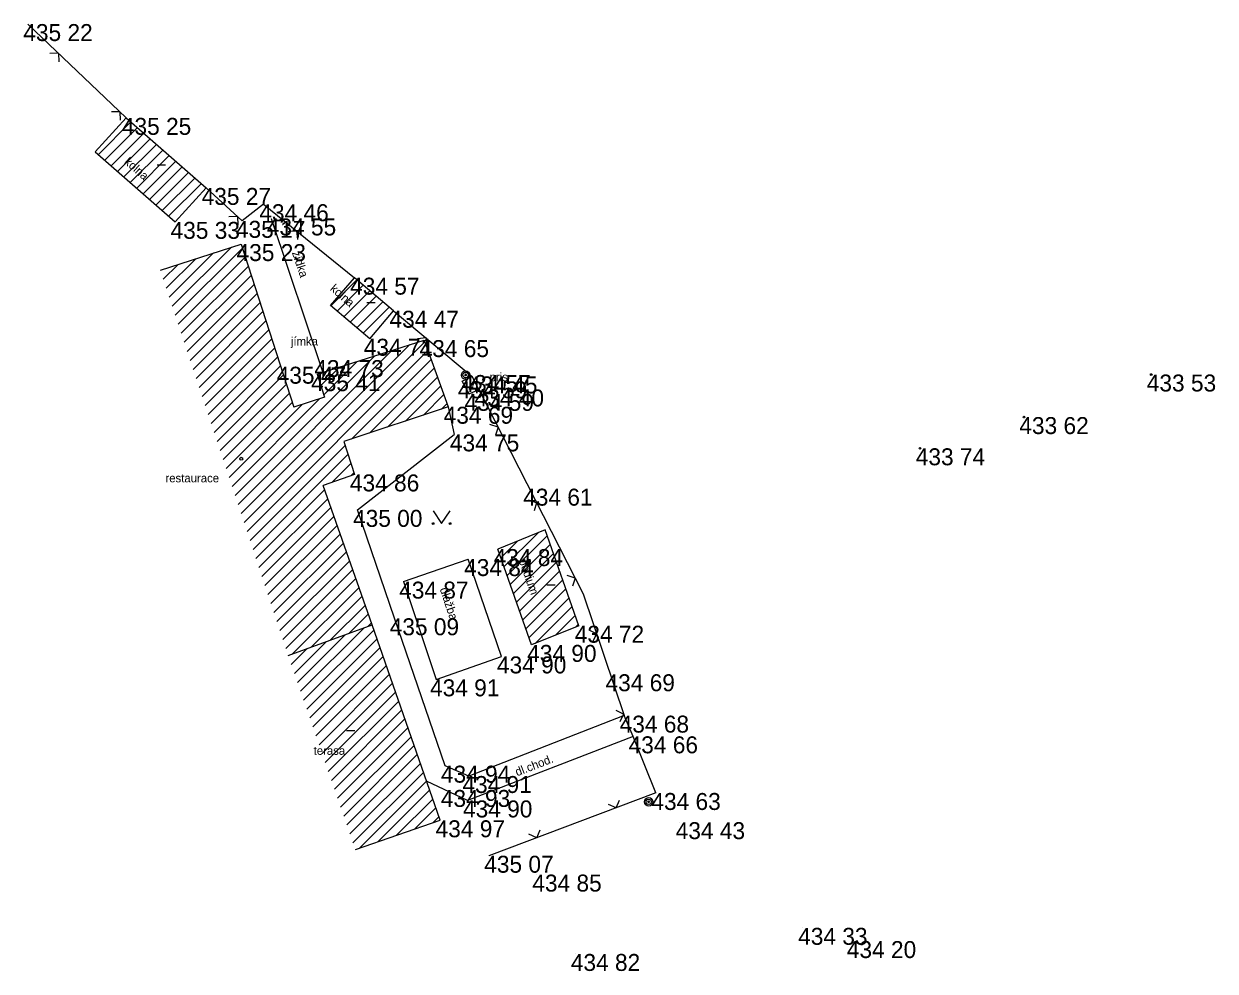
# Model space of a CAD drawing. Extents: x -554123 to -553118, y -1076825 to -1073672.
# Drawn here: x -554023.6 to -553953.4, y -1074082.7 to -1074026.9 of the extents above; entities that cross this region are included whole.
import ezdxf

# ---------------------------------------------------------------- set-up
doc = ezdxf.new("R2010")
doc.units = 0
for name, color, linetype in [('1', 7, 'Continuous'), ('12', 7, 'Continuous'), ('14', 7, 'Continuous'), ('17', 7, 'Continuous'), ('18', 7, 'Continuous'), ('20', 7, 'Continuous'), ('32', 7, 'Continuous'), ('45', 7, 'Continuous'), ('47', 7, 'Continuous'), ('52', 7, 'Continuous'), ('6', 7, 'Continuous')]:
    doc.layers.add(name, color=color, linetype=linetype)

# ---------------------------------------------------------------- blocks, each defined once
blk = doc.blocks.new('POINT_DISPLAY')
blk.add_line((0, 0), (0, 0))
blk = doc.blocks.new('T')
at = {"layer": '6'}
blk.add_circle((0, 0), 0.05, dxfattribs=at)
blk = doc.blocks.new('SLB')
at = {"layer": '20'}
for radius in [0.25, 0.158, 0.05]:
    blk.add_circle((0, 0), radius, dxfattribs=at)
blk = doc.blocks.new('BN')
at = {"layer": '47'}
blk.add_line((-0.25, 0), (0.25, 0), dxfattribs=at)
blk = doc.blocks.new('BZ')
at = {"layer": '47'}
blk.add_circle((0, 0), 0.0875, dxfattribs=at)
blk = doc.blocks.new('PARK')
at = {"layer": '45'}
for p, q in [((-0.5, 0.75), (0, 0)), ((0, 0), (0.5, 0.75))]:
    blk.add_line(p, q, dxfattribs=at)
for centre in [(-0.5, 0), (0.5, 0)]:
    blk.add_circle(centre, 0.05, dxfattribs=at)

msp = doc.modelspace()

# ---------------------------------------------------------------- linework, layer by layer
at = {"layer": '12'}
for p, q in [((-554023.41, -1074026.87), (-554017.6, -1074032.4)), ((-554021.599, -1074028.594), (-554022.1, -1074028.606)), ((-554021.599, -1074028.594), (-554021.587, -1074029.094)), ((-554017.977, -1074032.041), (-554018.478, -1074032.053)), ((-554017.977, -1074032.041), (-554017.965, -1074032.541)), ((-554012.9, -1074036.53), (-554010.77, -1074038.47)), ((-554009.51, -1074037.49), (-554010.77, -1074038.47)), ((-554009.51, -1074037.49), (-554004.16, -1074041.82)), ((-554011.052, -1074038.213), (-554011.552, -1074038.237)), ((-554011.052, -1074038.213), (-554011.028, -1074038.713)), ((-554007.567, -1074039.063), (-554008.065, -1074039.115)), ((-554007.567, -1074039.063), (-554007.514, -1074039.561)), ((-554001.85, -1074043.77), (-553997.22, -1074047.64)), ((-553999.932, -1074045.373), (-554000.43, -1074045.418)), ((-553999.932, -1074045.373), (-553999.887, -1074045.872)), ((-553996.83, -1074048.41), (-553990.676, -1074060.449)), ((-553995.692, -1074050.636), (-553996.168, -1074050.482)), ((-553995.692, -1074050.636), (-553995.846, -1074051.112)), ((-553993.416, -1074055.088), (-553993.893, -1074054.934)), ((-553993.416, -1074055.088), (-553993.57, -1074055.564)), ((-553991.141, -1074059.54), (-553991.617, -1074059.386)), ((-553991.141, -1074059.54), (-553991.295, -1074060.016)), ((-553990.676, -1074060.449), (-553988.26, -1074067.64)), ((-553989.88, -1074062.819), (-553990.328, -1074062.596)), ((-553989.88, -1074062.819), (-553990.103, -1074063.267)), ((-553988.287, -1074067.558), (-553988.736, -1074067.336)), ((-553988.287, -1074067.558), (-553988.51, -1074068.007)), ((-553987.72, -1074068.86), (-553988.26, -1074067.64)), ((-553986.39, -1074072.2), (-553987.72, -1074068.86)), ((-553986.39, -1074072.2), (-553996.24, -1074075.9)), ((-553988.73, -1074073.079), (-553989.186, -1074072.872)), ((-553988.73, -1074073.079), (-553988.523, -1074072.623)), ((-553993.411, -1074074.837), (-553993.204, -1074074.381)), ((-553993.411, -1074074.837), (-553993.867, -1074074.63))]:
    msp.add_line(p, q, dxfattribs=at)
at = {"layer": '14'}
for p, q in [((-554017.6, -1074032.4), (-554019.43, -1074034.4)), ((-554017.6, -1074032.4), (-554012.9, -1074036.53)), ((-554019.43, -1074034.4), (-554014.73, -1074038.53)), ((-554012.9, -1074036.53), (-554014.73, -1074038.53)), ((-554015.595, -1074041.385), (-554010.84, -1074039.84)), ((-554010.84, -1074039.84), (-554007.718, -1074049.447)), ((-554005.56, -1074043.47), (-554004.16, -1074041.82)), ((-554001.85, -1074043.77), (-554004.16, -1074041.82)), ((-554003.25, -1074045.42), (-554005.56, -1074043.47)), ((-554003.25, -1074045.42), (-554001.85, -1074043.77)), ((-554006.35, -1074047.51), (-554000.05, -1074045.5)), ((-554000.05, -1074045.5), (-553998.62, -1074049.43)), ((-554006.35, -1074047.51), (-554005.911, -1074048.86)), ((-554005.911, -1074048.86), (-554007.718, -1074049.447)), ((-553998.62, -1074049.43), (-554004.777, -1074051.485)), ((-554004.777, -1074051.485), (-554004.16, -1074053.42)), ((-554004.16, -1074053.42), (-554006.006, -1074054.074)), ((-554003.1, -1074062.28), (-554006.006, -1074054.074)), ((-553992.92, -1074056.69), (-553995.71, -1074057.82)), ((-553990.92, -1074062.34), (-553992.92, -1074056.69)), ((-553993.71, -1074063.47), (-553995.71, -1074057.82)), ((-554008.057, -1074064.101), (-554003.1, -1074062.28)), ((-553999.11, -1074073.81), (-554003.1, -1074062.28)), ((-553990.92, -1074062.34), (-553993.71, -1074063.47)), ((-554004.1, -1074075.537), (-553999.11, -1074073.81))]:
    msp.add_line(p, q, dxfattribs=at)
at = {"layer": '17'}
for p, q in [((-553998.62, -1074049.43), (-553998.28, -1074051.06)), ((-554003.97, -1074055.51), (-553998.28, -1074051.06)), ((-554001.8, -1074061.9), (-554003.97, -1074055.51)), ((-554001.27, -1074059.74), (-553997.45, -1074058.41)), ((-553995.49, -1074064.15), (-553997.45, -1074058.41)), ((-554001.27, -1074059.74), (-553999.33, -1074065.5)), ((-553998.81, -1074070.59), (-554001.8, -1074061.9)), ((-553999.33, -1074065.5), (-553995.49, -1074064.15)), ((-553988.26, -1074067.64), (-553997.42, -1074071.2)), ((-553987.72, -1074068.86), (-553997.49, -1074072.64)), ((-553997.42, -1074071.2), (-553998.81, -1074070.59)), ((-553997.49, -1074072.64), (-553999.911, -1074071.494))]:
    msp.add_line(p, q, dxfattribs=at)
at = {"layer": '18'}
for p, q in [((-554009.07, -1074038.33), (-554006.026, -1074047.407)), ((-553997.8, -1074047.93), (-553997.22, -1074047.64)), ((-553996.83, -1074048.41), (-553997.22, -1074047.64)), ((-553997.4, -1074048.67), (-553997.8, -1074047.93)), ((-553997.4, -1074048.67), (-553996.83, -1074048.41))]:
    msp.add_line(p, q, dxfattribs=at)
at = {"layer": '32'}
for p, q in [((-554019.247, -1074034.561), (-554017.326, -1074032.641)), ((-554018.87, -1074034.892), (-554016.95, -1074032.971)), ((-554018.494, -1074035.223), (-554016.573, -1074033.302)), ((-554018.117, -1074035.553), (-554016.197, -1074033.633)), ((-554017.741, -1074035.884), (-554015.821, -1074033.964)), ((-554017.365, -1074036.215), (-554015.444, -1074034.294)), ((-554016.988, -1074036.546), (-554015.068, -1074034.625)), ((-554016.612, -1074036.876), (-554014.691, -1074034.956)), ((-554016.236, -1074037.207), (-554014.315, -1074035.287)), ((-554015.859, -1074037.538), (-554013.939, -1074035.617)), ((-554015.483, -1074037.869), (-554013.562, -1074035.948)), ((-554015.106, -1074038.199), (-554013.186, -1074036.279)), ((-554014.89, -1074043.509), (-554011.405, -1074040.024)), ((-554014.714, -1074044.04), (-554010.76, -1074040.086)), ((-554015.243, -1074042.447), (-554013.5, -1074040.704)), ((-554015.066, -1074042.978), (-554012.453, -1074040.364)), ((-554014.538, -1074044.571), (-554010.587, -1074040.619)), ((-554015.419, -1074041.916), (-554014.548, -1074041.045)), ((-554014.362, -1074045.101), (-554010.413, -1074041.153)), ((-554014.186, -1074045.632), (-554010.24, -1074041.687)), ((-554014.009, -1074046.163), (-554010.066, -1074042.22)), ((-554005.551, -1074043.478), (-554004.015, -1074041.942)), ((-554005.167, -1074043.802), (-554003.632, -1074042.266)), ((-554013.833, -1074046.694), (-554009.893, -1074042.754)), ((-554004.784, -1074044.125), (-554003.248, -1074042.59)), ((-554004.4, -1074044.449), (-554002.865, -1074042.913)), ((-554013.657, -1074047.225), (-554009.72, -1074043.288)), ((-554004.017, -1074044.773), (-554002.481, -1074043.237)), ((-554003.633, -1074045.096), (-554002.098, -1074043.561)), ((-554013.481, -1074047.756), (-554009.546, -1074043.821)), ((-554013.305, -1074048.287), (-554009.373, -1074044.355)), ((-554013.128, -1074048.818), (-554009.199, -1074044.889)), ((-554012.952, -1074049.349), (-554009.026, -1074045.422)), ((-554010.838, -1074055.72), (-554000.884, -1074045.766)), ((-554010.662, -1074056.251), (-554000.013, -1074045.602)), ((-554012.776, -1074049.88), (-554008.852, -1074045.956)), ((-554011.19, -1074054.658), (-554002.961, -1074046.429)), ((-554011.014, -1074055.189), (-554001.923, -1074046.097)), ((-554010.486, -1074056.782), (-553999.824, -1074046.12)), ((-554012.6, -1074050.411), (-554008.679, -1074046.49)), ((-554012.424, -1074050.942), (-554008.506, -1074047.023)), ((-554006.131, -1074048.184), (-554005.038, -1074047.091)), ((-554005.957, -1074048.718), (-554004, -1074046.76)), ((-554004.334, -1074051.337), (-553999.636, -1074046.639)), ((-554003.273, -1074050.983), (-553999.447, -1074047.157)), ((-554012.248, -1074051.473), (-554008.332, -1074047.557)), ((-554006.304, -1074047.651), (-554006.076, -1074047.423)), ((-554002.211, -1074050.629), (-553999.258, -1074047.676)), ((-554012.071, -1074052.004), (-554008.159, -1074048.091)), ((-554001.15, -1074050.274), (-553999.07, -1074048.194)), ((-554011.895, -1074052.534), (-554007.985, -1074048.625)), ((-554011.719, -1074053.065), (-554007.812, -1074049.158)), ((-554011.543, -1074053.596), (-554007.237, -1074049.291)), ((-554011.367, -1074054.127), (-554006.19, -1074048.951)), ((-554000.089, -1074049.92), (-553998.881, -1074048.713)), ((-553999.027, -1074049.566), (-553998.692, -1074049.231)), ((-554010.31, -1074057.313), (-554004.706, -1074051.709)), ((-554010.133, -1074057.844), (-554004.535, -1074052.245)), ((-554005.465, -1074053.882), (-554004.364, -1074052.781)), ((-554004.37, -1074053.494), (-554004.193, -1074053.317)), ((-554009.957, -1074058.375), (-554005.915, -1074054.332)), ((-554009.781, -1074058.906), (-554005.73, -1074054.854)), ((-554009.605, -1074059.436), (-554005.545, -1074055.376)), ((-554009.429, -1074059.967), (-554005.36, -1074055.899)), ((-554009.252, -1074060.498), (-554005.175, -1074056.421)), ((-554009.076, -1074061.029), (-554004.99, -1074056.943)), ((-553995.34, -1074058.864), (-553993.333, -1074056.857)), ((-554008.9, -1074061.56), (-554004.805, -1074057.465)), ((-553995.525, -1074058.342), (-553994.522, -1074057.339)), ((-553995.155, -1074059.387), (-553992.799, -1074057.031)), ((-553994.971, -1074059.909), (-553992.615, -1074057.553)), ((-554008.724, -1074062.091), (-554004.62, -1074057.987)), ((-553994.786, -1074060.431), (-553992.43, -1074058.075)), ((-554008.548, -1074062.622), (-554004.435, -1074058.51)), ((-554008.372, -1074063.153), (-554004.25, -1074059.032)), ((-553994.601, -1074060.953), (-553992.245, -1074058.597)), ((-553994.416, -1074061.476), (-553992.06, -1074059.12)), ((-554008.195, -1074063.684), (-554004.065, -1074059.554)), ((-553994.231, -1074061.998), (-553991.875, -1074059.642)), ((-554007.817, -1074064.013), (-554003.88, -1074060.076)), ((-553994.046, -1074062.52), (-553991.69, -1074060.164)), ((-554006.7, -1074063.602), (-554003.696, -1074060.598)), ((-554005.582, -1074063.192), (-554003.511, -1074061.12)), ((-553993.861, -1074063.042), (-553991.505, -1074060.686)), ((-553993.495, -1074063.383), (-553991.32, -1074061.209)), ((-554004.464, -1074062.781), (-554003.326, -1074061.643)), ((-553992.306, -1074062.901), (-553991.136, -1074061.731)), ((-554007.33, -1074066.202), (-554003.586, -1074062.459)), ((-554007.148, -1074066.728), (-554002.997, -1074062.577)), ((-554003.347, -1074062.371), (-554003.141, -1074062.165)), ((-553991.118, -1074062.42), (-553990.951, -1074062.253)), ((-554007.693, -1074065.152), (-554005.822, -1074063.28)), ((-554007.512, -1074065.677), (-554004.704, -1074062.869)), ((-554006.966, -1074067.253), (-554002.815, -1074063.102)), ((-554007.875, -1074064.626), (-554006.939, -1074063.69)), ((-554006.785, -1074067.778), (-554002.634, -1074063.627)), ((-554006.603, -1074068.304), (-554002.452, -1074064.153)), ((-554006.421, -1074068.829), (-554002.27, -1074064.678)), ((-554006.239, -1074069.354), (-554002.088, -1074065.203)), ((-554006.058, -1074069.88), (-554001.907, -1074065.729)), ((-554005.876, -1074070.405), (-554001.725, -1074066.254)), ((-554005.694, -1074070.93), (-554001.543, -1074066.779)), ((-554005.512, -1074071.456), (-554001.361, -1074067.305)), ((-554005.33, -1074071.981), (-554001.179, -1074067.83)), ((-554005.149, -1074072.506), (-554000.998, -1074068.355)), ((-554004.967, -1074073.032), (-554000.816, -1074068.881)), ((-554004.785, -1074073.557), (-554000.634, -1074069.406)), ((-554004.603, -1074074.082), (-554000.452, -1074069.931)), ((-554004.422, -1074074.608), (-554000.27, -1074070.457)), ((-554004.24, -1074075.133), (-554000.089, -1074070.982)), ((-554003.85, -1074075.451), (-553999.907, -1074071.507)), ((-554002.769, -1074075.076), (-553999.725, -1074072.033)), ((-554001.687, -1074074.702), (-553999.543, -1074072.558)), ((-554000.606, -1074074.328), (-553999.362, -1074073.083)), ((-553999.525, -1074073.954), (-553999.18, -1074073.609))]:
    msp.add_line(p, q, dxfattribs=at)

# ---------------------------------------------------------------- block references
at = {"layer": '1'}
for p in [(-554023.41, -1074026.87), (-554017.6, -1074032.4), (-554012.9, -1074036.53), (-554009.51, -1074037.49), (-554014.73, -1074038.53), (-554010.77, -1074038.47), (-554009.07, -1074038.33), (-554010.84, -1074039.84), (-554004.16, -1074041.82), (-554001.85, -1074043.77), (-554003.25, -1074045.42), (-554000.05, -1074045.5), (-554008.49, -1074047.07), (-554006.27, -1074046.68), (-554006.35, -1074047.51), (-553997.6, -1074047.56), (-553997.22, -1074047.64), (-553957.19, -1074047.53), (-553997.8, -1074047.93), (-553996.83, -1074048.41), (-553997.4, -1074048.67), (-553998.62, -1074049.43), (-553964.69, -1074050.04), (-553998.28, -1074051.06), (-553970.82, -1074051.88), (-554004.16, -1074053.42), (-553993.84, -1074054.26), (-554003.97, -1074055.51), (-553997.45, -1074058.41), (-553995.71, -1074057.82), (-554001.27, -1074059.74), (-554001.8, -1074061.9), (-554003.1, -1074062.28), (-553990.92, -1074062.34), (-553993.71, -1074063.47), (-553995.49, -1074064.15), (-553989.08, -1074065.2), (-553999.33, -1074065.5), (-553988.26, -1074067.64), (-553987.72, -1074068.86), (-553998.81, -1074070.59), (-553997.42, -1074071.2), (-553998.8, -1074072.02), (-553986.39, -1074072.2), (-553997.49, -1074072.64), (-553986.81, -1074072.72), (-553999.11, -1074073.81), (-553984.98, -1074073.92), (-553996.24, -1074075.9), (-553993.42, -1074077.01), (-553977.75, -1074080.15), (-553974.88, -1074080.93), (-553991.15, -1074081.69)]:
    msp.add_blockref('POINT_DISPLAY', p, dxfattribs=at)
at = {"layer": '20'}
for p in [(-553997.6, -1074047.56), (-553986.81, -1074072.72)]:
    msp.add_blockref('SLB', p, dxfattribs=at)
at = {"layer": '32'}
for p in [(-554015.595, -1074041.385), (-553995.71, -1074057.82), (-554008.057, -1074064.101)]:
    msp.add_blockref('POINT_DISPLAY', p, dxfattribs=at)
at = {"layer": '45'}
msp.add_blockref('PARK', (-553999.017, -1074056.315), dxfattribs=at)
at = {"layer": '47'}
for name, p in [('BN', (-554015.537, -1074035.166)), ('BN', (-554003.18, -1074043.283)), ('BZ', (-554010.827, -1074052.495)), ('BN', (-553992.564, -1074059.938)), ('BN', (-554004.376, -1074068.51))]:
    msp.add_blockref(name, p, dxfattribs=at)
at = {"layer": '6'}
for p in [(-553957.19, -1074047.53), (-553964.69, -1074050.04), (-553970.82, -1074051.88)]:
    msp.add_blockref('T', p, dxfattribs=at)

# ---------------------------------------------------------------- texts
at = {"layer": '52'}
for s, rotation, p in [('kolna', 318.69347, (-554017.76, -1074035.048)), ('zídka', 288.53904, (-554007.845, -1074040.341)), ('kolna', 318.69347, (-554005.628, -1074042.527)), ('podium', 289.49306, (-553994.476, -1074058.496)), ('dlažba', 288.61381, (-553999.136, -1074060.177)), ('dl.chod.', 21.15139, (-553994.563, -1074071.219))]:
    msp.add_text(s, height=0.5, rotation=rotation, dxfattribs=at).set_placement(p)
for s, p in [('jímka', (-554007.899, -1074045.819)), ('pris', (-553996.186, -1074047.925)), ('restaurace', (-554015.293, -1074053.884)), ('terasa', (-554006.559, -1074069.949))]:
    msp.add_text(s, height=0.5, dxfattribs=at).set_placement(p)
at = {"layer": '6'}
for s, p in [('435 22 ', (-554023.672, -1074027.87)), ('435 25 ', (-554017.862, -1074033.4)), ('435 27 ', (-554013.16, -1074037.53)), ('434 46 ', (-554009.76, -1074038.49)), ('435 33 ', (-554014.992, -1074039.53)), ('435 17 ', (-554011.139, -1074039.47)), ('434 55 ', (-554009.32, -1074039.33)), ('435 23 ', (-554011.102, -1074040.84)), ('434 57 ', (-554004.408, -1074042.82)), ('434 47 ', (-554002.086, -1074044.77)), ('434 71 ', (-554003.605, -1074046.42)), ('434 65 ', (-554000.312, -1074046.5)), ('435 47 ', (-554008.738, -1074048.07)), ('434 73 ', (-554006.518, -1074047.68)), ('435 41 ', (-554006.707, -1074048.51)), ('434 57 ', (-553997.848, -1074048.56)), ('434 45 ', (-553997.458, -1074048.64)), ('433 53 ', (-553957.452, -1074048.53)), ('434 59 ', (-553998.062, -1074048.93)), ('434 40 ', (-553997.07, -1074049.41)), ('434 59 ', (-553997.662, -1074049.67)), ('434 69 ', (-553998.894, -1074050.43)), ('433 62 ', (-553964.964, -1074051.04)), ('434 75 ', (-553998.528, -1074052.06)), ('433 74 ', (-553971.068, -1074052.88)), ('434 86 ', (-554004.422, -1074054.42)), ('434 61 ', (-553994.209, -1074055.26)), ('435 00 ', (-554004.236, -1074056.51)), ('434 84 ', (-553997.688, -1074059.41)), ('434 84 ', (-553995.948, -1074058.82)), ('434 87 ', (-554001.518, -1074060.74)), ('435 09 ', (-554002.076, -1074062.9)), ('434 72 ', (-553991.168, -1074063.34)), ('434 90 ', (-553993.974, -1074064.47)), ('434 90 ', (-553995.754, -1074065.15)), ('434 69 ', (-553989.354, -1074066.2)), ('434 91 ', (-553999.699, -1074066.5)), ('434 68 ', (-553988.522, -1074068.64)), ('434 66 ', (-553987.994, -1074069.86)), ('434 94 ', (-553999.06, -1074071.59)), ('434 91 ', (-553997.789, -1074072.2)), ('434 93 ', (-553999.062, -1074073.02)), ('434 63 ', (-553986.652, -1074073.2)), ('434 90 ', (-553997.754, -1074073.64)), ('434 97 ', (-553999.37, -1074074.81)), ('434 43 ', (-553985.218, -1074074.92)), ('435 07 ', (-553996.502, -1074076.9)), ('434 85 ', (-553993.67, -1074078.01)), ('434 33 ', (-553978, -1074081.15)), ('434 20 ', (-553975.132, -1074081.93)), ('434 82 ', (-553991.4, -1074082.69))]:
    msp.add_text(s, height=1, dxfattribs=at).set_placement(p)

doc.saveas('drawing.dxf')
